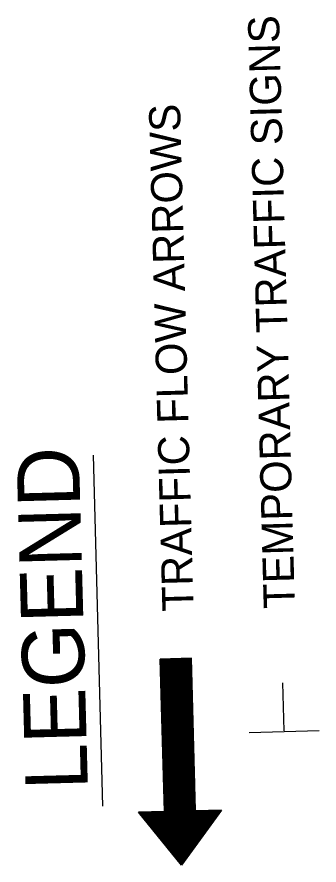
# Model space of a CAD drawing. Extents: x 1929653 to 1931621, y 596452 to 600944.
# Drawn here: x 1930592.3 to 1930650.5, y 599466.7 to 599629.8 of the extents above; entities that cross this region are included whole.
import ezdxf

# ---------------------------------------------------------------- set-up
doc = ezdxf.new("R2010")
doc.units = 0
for name, color, linetype in [('R_Border', 7, 'Continuous'), ('R_Draft', 7, 'Continuous'), ('R_Legend_MOT', 7, 'Continuous')]:
    doc.layers.add(name, color=color, linetype=linetype)

msp = doc.modelspace()

# ---------------------------------------------------------------- linework, layer by layer
at = {"layer": 'R_Border'}
for p, q in [((1930620.05, 599506.36), (1930626.06, 599500.66)), ((1930620.19, 599506.36), (1930626.06, 599500.8)), ((1930620.33, 599506.36), (1930626.05, 599500.94)), ((1930620.47, 599506.37), (1930626.05, 599501.08)), ((1930620.61, 599506.37), (1930626.05, 599501.22)), ((1930620.75, 599506.37), (1930626.04, 599501.36)), ((1930620.9, 599506.38), (1930626.04, 599501.5)), ((1930621.04, 599506.38), (1930626.04, 599501.64)), ((1930621.18, 599506.39), (1930626.03, 599501.79)), ((1930621.32, 599506.39), (1930626.03, 599501.93)), ((1930621.46, 599506.39), (1930626.02, 599502.07)), ((1930621.6, 599506.4), (1930626.02, 599502.21)), ((1930621.74, 599506.4), (1930626.02, 599502.35)), ((1930621.89, 599506.41), (1930626.01, 599502.49)), ((1930622.03, 599506.41), (1930626.01, 599502.63)), ((1930622.17, 599506.41), (1930626.01, 599502.78)), ((1930622.31, 599506.42), (1930626, 599502.92)), ((1930622.45, 599506.42), (1930626, 599503.06)), ((1930622.59, 599506.42), (1930625.99, 599503.2)), ((1930622.73, 599506.43), (1930625.99, 599503.34)), ((1930622.87, 599506.43), (1930625.99, 599503.48)), ((1930623.02, 599506.44), (1930625.98, 599503.62)), ((1930623.16, 599506.44), (1930625.98, 599503.77)), ((1930623.3, 599506.44), (1930625.98, 599503.91)), ((1930623.44, 599506.45), (1930625.97, 599504.05)), ((1930623.58, 599506.45), (1930625.97, 599504.19)), ((1930623.72, 599506.45), (1930625.96, 599504.33)), ((1930623.86, 599506.46), (1930625.96, 599504.47)), ((1930624.01, 599506.46), (1930625.96, 599504.61)), ((1930624.15, 599506.47), (1930625.95, 599504.75)), ((1930624.29, 599506.47), (1930625.95, 599504.9)), ((1930624.43, 599506.47), (1930625.94, 599505.04)), ((1930624.57, 599506.48), (1930625.94, 599505.18)), ((1930624.71, 599506.48), (1930625.94, 599505.32)), ((1930624.85, 599506.48), (1930625.93, 599505.46)), ((1930625, 599506.49), (1930625.93, 599505.6)), ((1930625.14, 599506.49), (1930625.93, 599505.74)), ((1930625.28, 599506.5), (1930625.92, 599505.89)), ((1930625.42, 599506.5), (1930625.92, 599506.03)), ((1930625.56, 599506.5), (1930625.91, 599506.17)), ((1930625.7, 599506.51), (1930625.91, 599506.31)), ((1930625.84, 599506.51), (1930625.91, 599506.45)), ((1930619.92, 599506.34), (1930626.07, 599500.51)), ((1930619.93, 599506.19), (1930626.07, 599500.37)), ((1930619.93, 599506.05), (1930626.07, 599500.23)), ((1930619.93, 599505.91), (1930626.08, 599500.09)), ((1930619.94, 599505.77), (1930626.08, 599499.95)), ((1930619.94, 599505.63), (1930626.09, 599499.81)), ((1930619.95, 599505.49), (1930626.09, 599499.67)), ((1930619.95, 599505.35), (1930626.09, 599499.52)), ((1930619.95, 599505.2), (1930626.1, 599499.38)), ((1930619.96, 599505.06), (1930626.1, 599499.24)), ((1930619.96, 599504.92), (1930626.1, 599499.1)), ((1930619.96, 599504.78), (1930626.11, 599498.96)), ((1930619.97, 599504.64), (1930626.11, 599498.82)), ((1930619.97, 599504.5), (1930626.12, 599498.68)), ((1930619.98, 599504.36), (1930626.12, 599498.53)), ((1930619.98, 599504.22), (1930626.12, 599498.39)), ((1930619.98, 599504.07), (1930626.13, 599498.25)), ((1930619.99, 599503.93), (1930626.13, 599498.11)), ((1930619.99, 599503.79), (1930626.13, 599497.97)), ((1930620, 599503.65), (1930626.14, 599497.83)), ((1930620, 599503.51), (1930626.14, 599497.69)), ((1930620, 599503.37), (1930626.15, 599497.55)), ((1930620.01, 599503.23), (1930626.15, 599497.4)), ((1930620.01, 599503.08), (1930626.15, 599497.26)), ((1930620.01, 599502.94), (1930626.16, 599497.12)), ((1930620.02, 599502.8), (1930626.16, 599496.98)), ((1930620.02, 599502.66), (1930626.16, 599496.84)), ((1930620.03, 599502.52), (1930626.17, 599496.7)), ((1930620.03, 599502.38), (1930626.17, 599496.56)), ((1930620.03, 599502.24), (1930626.18, 599496.41)), ((1930620.04, 599502.09), (1930626.18, 599496.27)), ((1930620.04, 599501.95), (1930626.18, 599496.13)), ((1930620.04, 599501.81), (1930626.19, 599495.99)), ((1930620.05, 599501.67), (1930626.19, 599495.85)), ((1930620.05, 599501.53), (1930626.2, 599495.71)), ((1930620.06, 599501.39), (1930626.2, 599495.57)), ((1930620.06, 599501.25), (1930626.2, 599495.42)), ((1930620.06, 599501.11), (1930626.21, 599495.28)), ((1930620.07, 599500.96), (1930626.21, 599495.14)), ((1930620.07, 599500.82), (1930626.21, 599495)), ((1930620.07, 599500.68), (1930626.22, 599494.86)), ((1930620.08, 599500.54), (1930626.22, 599494.72)), ((1930620.08, 599500.4), (1930626.23, 599494.58)), ((1930620.09, 599500.26), (1930626.23, 599494.43)), ((1930620.09, 599500.12), (1930626.23, 599494.29)), ((1930620.09, 599499.97), (1930626.24, 599494.15)), ((1930620.1, 599499.83), (1930626.24, 599494.01)), ((1930620.1, 599499.69), (1930626.24, 599493.87)), ((1930620.11, 599499.55), (1930626.25, 599493.73)), ((1930620.11, 599499.41), (1930626.25, 599493.59)), ((1930620.11, 599499.27), (1930626.26, 599493.45)), ((1930620.12, 599499.13), (1930626.26, 599493.3)), ((1930620.12, 599498.98), (1930626.26, 599493.16)), ((1930620.12, 599498.84), (1930626.27, 599493.02)), ((1930620.13, 599498.7), (1930626.27, 599492.88)), ((1930620.13, 599498.56), (1930626.27, 599492.74)), ((1930620.14, 599498.42), (1930626.28, 599492.6)), ((1930620.14, 599498.28), (1930626.28, 599492.46)), ((1930620.14, 599498.14), (1930626.29, 599492.31)), ((1930620.15, 599497.99), (1930626.29, 599492.17)), ((1930620.15, 599497.85), (1930626.29, 599492.03)), ((1930620.15, 599497.71), (1930626.3, 599491.89)), ((1930620.16, 599497.57), (1930626.3, 599491.75)), ((1930620.16, 599497.43), (1930626.31, 599491.61)), ((1930620.17, 599497.29), (1930626.31, 599491.47)), ((1930620.17, 599497.15), (1930626.31, 599491.32)), ((1930620.17, 599497.01), (1930626.32, 599491.18)), ((1930620.18, 599496.86), (1930626.32, 599491.04)), ((1930620.18, 599496.72), (1930626.32, 599490.9)), ((1930620.19, 599496.58), (1930626.33, 599490.76)), ((1930620.19, 599496.44), (1930626.33, 599490.62)), ((1930620.19, 599496.3), (1930626.34, 599490.48)), ((1930620.2, 599496.16), (1930626.34, 599490.34)), ((1930620.2, 599496.02), (1930626.34, 599490.19)), ((1930620.2, 599495.87), (1930626.35, 599490.05)), ((1930620.21, 599495.73), (1930626.35, 599489.91)), ((1930620.21, 599495.59), (1930626.35, 599489.77)), ((1930620.22, 599495.45), (1930626.36, 599489.63)), ((1930620.22, 599495.31), (1930626.36, 599489.49)), ((1930620.22, 599495.17), (1930626.37, 599489.35)), ((1930620.23, 599495.03), (1930626.37, 599489.2)), ((1930620.23, 599494.88), (1930626.37, 599489.06)), ((1930620.23, 599494.74), (1930626.38, 599488.92)), ((1930620.24, 599494.6), (1930626.38, 599488.78)), ((1930620.24, 599494.46), (1930626.39, 599488.64)), ((1930620.25, 599494.32), (1930626.39, 599488.5)), ((1930620.25, 599494.18), (1930626.39, 599488.36)), ((1930620.25, 599494.04), (1930626.4, 599488.21)), ((1930620.26, 599493.9), (1930626.4, 599488.07)), ((1930620.26, 599493.75), (1930626.4, 599487.93)), ((1930620.26, 599493.61), (1930626.41, 599487.79)), ((1930620.27, 599493.47), (1930626.41, 599487.65)), ((1930620.27, 599493.33), (1930626.42, 599487.51)), ((1930620.28, 599493.19), (1930626.42, 599487.37)), ((1930620.28, 599493.05), (1930626.42, 599487.23)), ((1930620.28, 599492.91), (1930626.43, 599487.08)), ((1930620.29, 599492.76), (1930626.43, 599486.94)), ((1930620.29, 599492.62), (1930626.43, 599486.8)), ((1930620.3, 599492.48), (1930626.44, 599486.66)), ((1930620.3, 599492.34), (1930626.44, 599486.52)), ((1930620.3, 599492.2), (1930626.45, 599486.38)), ((1930620.31, 599492.06), (1930626.45, 599486.24)), ((1930620.31, 599491.92), (1930626.45, 599486.09)), ((1930620.31, 599491.77), (1930626.46, 599485.95)), ((1930620.32, 599491.63), (1930626.46, 599485.81)), ((1930620.32, 599491.49), (1930626.46, 599485.67)), ((1930620.33, 599491.35), (1930626.47, 599485.53)), ((1930620.33, 599491.21), (1930626.47, 599485.39)), ((1930620.33, 599491.07), (1930626.48, 599485.25)), ((1930620.34, 599490.93), (1930626.48, 599485.1)), ((1930620.34, 599490.78), (1930626.48, 599484.96)), ((1930620.34, 599490.64), (1930626.49, 599484.82)), ((1930620.35, 599490.5), (1930626.49, 599484.68)), ((1930620.35, 599490.36), (1930626.5, 599484.54)), ((1930620.36, 599490.22), (1930626.5, 599484.4)), ((1930620.36, 599490.08), (1930626.5, 599484.26)), ((1930620.36, 599489.94), (1930626.51, 599484.11)), ((1930620.37, 599489.8), (1930626.51, 599483.97)), ((1930620.37, 599489.65), (1930626.51, 599483.83)), ((1930620.37, 599489.51), (1930626.52, 599483.69)), ((1930620.38, 599489.37), (1930626.52, 599483.55)), ((1930620.38, 599489.23), (1930626.53, 599483.41)), ((1930620.39, 599489.09), (1930626.53, 599483.27)), ((1930620.39, 599488.95), (1930626.53, 599483.13)), ((1930620.39, 599488.81), (1930626.54, 599482.98)), ((1930620.4, 599488.66), (1930626.54, 599482.84)), ((1930620.4, 599488.52), (1930626.54, 599482.7)), ((1930620.41, 599488.38), (1930626.55, 599482.56)), ((1930620.41, 599488.24), (1930626.55, 599482.42)), ((1930620.41, 599488.1), (1930626.56, 599482.28)), ((1930620.42, 599487.96), (1930626.56, 599482.14)), ((1930620.42, 599487.82), (1930626.56, 599481.99)), ((1930620.42, 599487.67), (1930626.57, 599481.85)), ((1930620.43, 599487.53), (1930626.57, 599481.71)), ((1930620.43, 599487.39), (1930626.57, 599481.57)), ((1930620.44, 599487.25), (1930626.58, 599481.43)), ((1930620.44, 599487.11), (1930626.58, 599481.29)), ((1930620.44, 599486.97), (1930626.59, 599481.15)), ((1930620.45, 599486.83), (1930626.59, 599481)), ((1930620.45, 599486.69), (1930626.59, 599480.86)), ((1930620.45, 599486.54), (1930626.6, 599480.72)), ((1930620.46, 599486.4), (1930626.6, 599480.58)), ((1930620.46, 599486.26), (1930626.61, 599480.44)), ((1930620.47, 599486.12), (1930626.61, 599480.3)), ((1930620.47, 599485.98), (1930626.61, 599480.16)), ((1930620.47, 599485.84), (1930626.62, 599480.02)), ((1930620.48, 599485.7), (1930626.62, 599479.87)), ((1930620.48, 599485.55), (1930626.62, 599479.73)), ((1930620.48, 599485.41), (1930626.63, 599479.59)), ((1930620.49, 599485.27), (1930626.63, 599479.45)), ((1930620.49, 599485.13), (1930626.64, 599479.31)), ((1930620.5, 599484.99), (1930626.64, 599479.17)), ((1930620.5, 599484.85), (1930626.64, 599479.03)), ((1930620.5, 599484.71), (1930626.65, 599478.88)), ((1930620.51, 599484.56), (1930626.65, 599478.74)), ((1930620.51, 599484.42), (1930626.65, 599478.6)), ((1930620.52, 599484.28), (1930626.66, 599478.46)), ((1930620.52, 599484.14), (1930626.66, 599478.32)), ((1930620.52, 599484), (1930626.67, 599478.18)), ((1930620.53, 599483.86), (1930626.67, 599478.04)), ((1930620.53, 599483.72), (1930626.67, 599477.89)), ((1930620.53, 599483.58), (1930626.68, 599477.75)), ((1930620.54, 599483.43), (1930626.68, 599477.61)), ((1930620.54, 599483.29), (1930626.68, 599477.47)), ((1930620.55, 599483.15), (1930626.69, 599477.33)), ((1930620.55, 599483.01), (1930626.69, 599477.19)), ((1930620.55, 599482.87), (1930629.53, 599474.36)), ((1930620.56, 599482.73), (1930629.47, 599474.28)), ((1930620.56, 599482.59), (1930629.41, 599474.2)), ((1930620.56, 599482.44), (1930629.35, 599474.12)), ((1930620.57, 599482.3), (1930629.29, 599474.04)), ((1930620.57, 599482.16), (1930629.23, 599473.95)), ((1930620.58, 599482.02), (1930629.17, 599473.87)), ((1930620.58, 599481.88), (1930629.11, 599473.79)), ((1930620.58, 599481.74), (1930629.05, 599473.71)), ((1930620.59, 599481.6), (1930629, 599473.63)), ((1930620.59, 599481.45), (1930628.94, 599473.55)), ((1930620.59, 599481.31), (1930628.88, 599473.46)), ((1930620.6, 599481.17), (1930628.82, 599473.38)), ((1930620.6, 599481.03), (1930628.76, 599473.3)), ((1930620.61, 599480.89), (1930628.7, 599473.22)), ((1930620.61, 599480.75), (1930628.64, 599473.14)), ((1930620.61, 599480.61), (1930628.58, 599473.06)), ((1930620.62, 599480.46), (1930628.52, 599472.98)), ((1930620.62, 599480.32), (1930628.46, 599472.89)), ((1930620.63, 599480.18), (1930628.4, 599472.81)), ((1930620.63, 599480.04), (1930628.34, 599472.73)), ((1930620.63, 599479.9), (1930628.28, 599472.65)), ((1930620.64, 599479.76), (1930628.22, 599472.57)), ((1930620.64, 599479.62), (1930628.16, 599472.49)), ((1930620.64, 599479.48), (1930628.1, 599472.41)), ((1930620.65, 599479.33), (1930628.04, 599472.32)), ((1930620.65, 599479.19), (1930627.99, 599472.24)), ((1930620.66, 599479.05), (1930627.93, 599472.16)), ((1930620.66, 599478.91), (1930627.87, 599472.08)), ((1930620.66, 599478.77), (1930627.81, 599472)), ((1930620.34, 599477.01), (1930626.92, 599470.78)), ((1930620.48, 599477.01), (1930626.98, 599470.86)), ((1930620.63, 599477.01), (1930627.04, 599470.94)), ((1930620.67, 599478.63), (1930627.75, 599471.92)), ((1930620.67, 599478.49), (1930627.69, 599471.83)), ((1930620.67, 599478.34), (1930627.63, 599471.75)), ((1930620.68, 599478.2), (1930627.57, 599471.67)), ((1930620.68, 599478.06), (1930627.51, 599471.59)), ((1930620.69, 599477.92), (1930627.45, 599471.51)), ((1930620.69, 599477.78), (1930627.39, 599471.43)), ((1930620.69, 599477.64), (1930627.33, 599471.35)), ((1930620.7, 599477.5), (1930627.27, 599471.26)), ((1930620.7, 599477.35), (1930627.21, 599471.18)), ((1930620.7, 599477.21), (1930627.15, 599471.1)), ((1930620.71, 599477.07), (1930627.09, 599471.02)), ((1930626.7, 599477.18), (1930629.59, 599474.44)), ((1930626.85, 599477.18), (1930629.65, 599474.52)), ((1930626.99, 599477.18), (1930629.71, 599474.61)), ((1930627.13, 599477.19), (1930629.77, 599474.69)), ((1930627.27, 599477.19), (1930629.83, 599474.77)), ((1930627.41, 599477.2), (1930629.89, 599474.85)), ((1930627.55, 599477.2), (1930629.95, 599474.93)), ((1930627.69, 599477.2), (1930630, 599475.01)), ((1930627.84, 599477.21), (1930630.06, 599475.09)), ((1930627.98, 599477.21), (1930630.12, 599475.18)), ((1930628.12, 599477.21), (1930630.18, 599475.26)), ((1930628.26, 599477.22), (1930630.24, 599475.34)), ((1930628.4, 599477.22), (1930630.3, 599475.42)), ((1930628.54, 599477.23), (1930630.36, 599475.5)), ((1930628.68, 599477.23), (1930630.42, 599475.58)), ((1930628.82, 599477.23), (1930630.48, 599475.67)), ((1930628.97, 599477.24), (1930630.54, 599475.75)), ((1930629.11, 599477.24), (1930630.6, 599475.83)), ((1930629.25, 599477.24), (1930630.66, 599475.91)), ((1930629.39, 599477.25), (1930630.72, 599475.99)), ((1930629.53, 599477.25), (1930630.78, 599476.07)), ((1930629.67, 599477.26), (1930630.84, 599476.15)), ((1930629.81, 599477.26), (1930630.9, 599476.24)), ((1930629.96, 599477.26), (1930630.95, 599476.32)), ((1930630.1, 599477.27), (1930631.01, 599476.4)), ((1930630.24, 599477.27), (1930631.07, 599476.48)), ((1930630.38, 599477.28), (1930631.13, 599476.56)), ((1930630.52, 599477.28), (1930631.19, 599476.64)), ((1930630.66, 599477.28), (1930631.25, 599476.72)), ((1930630.8, 599477.29), (1930631.31, 599476.81)), ((1930630.95, 599477.29), (1930631.37, 599476.89)), ((1930631.09, 599477.29), (1930631.43, 599476.97)), ((1930631.23, 599477.3), (1930631.49, 599477.05)), ((1930631.37, 599477.3), (1930631.55, 599477.13)), ((1930631.51, 599477.31), (1930631.61, 599477.21)), ((1930631.65, 599477.31), (1930631.67, 599477.3)), ((1930615.82, 599476.88), (1930625.02, 599468.17)), ((1930615.89, 599476.68), (1930624.96, 599468.09)), ((1930615.96, 599476.89), (1930625.08, 599468.25)), ((1930616.1, 599476.89), (1930625.14, 599468.33)), ((1930616.24, 599476.9), (1930625.19, 599468.41)), ((1930616.38, 599476.9), (1930625.25, 599468.49)), ((1930616.38, 599476.08), (1930624.9, 599468)), ((1930616.53, 599476.9), (1930625.31, 599468.58)), ((1930616.67, 599476.91), (1930625.37, 599468.66)), ((1930616.81, 599476.91), (1930625.43, 599468.74)), ((1930616.87, 599475.47), (1930624.84, 599467.92)), ((1930616.95, 599476.91), (1930625.49, 599468.82)), ((1930617.09, 599476.92), (1930625.55, 599468.9)), ((1930617.23, 599476.92), (1930625.61, 599468.98)), ((1930617.37, 599476.93), (1930625.67, 599469.06)), ((1930617.52, 599476.93), (1930625.73, 599469.15)), ((1930617.66, 599476.93), (1930625.79, 599469.23)), ((1930617.8, 599476.94), (1930625.85, 599469.31)), ((1930617.94, 599476.94), (1930625.91, 599469.39)), ((1930618.08, 599476.95), (1930625.97, 599469.47)), ((1930618.22, 599476.95), (1930626.03, 599469.55)), ((1930618.36, 599476.95), (1930626.09, 599469.63)), ((1930618.5, 599476.96), (1930626.14, 599469.72)), ((1930618.65, 599476.96), (1930626.2, 599469.8)), ((1930618.79, 599476.96), (1930626.26, 599469.88)), ((1930618.93, 599476.97), (1930626.32, 599469.96)), ((1930619.07, 599476.97), (1930626.38, 599470.04)), ((1930619.21, 599476.98), (1930626.44, 599470.12)), ((1930619.35, 599476.98), (1930626.5, 599470.2)), ((1930619.49, 599476.98), (1930626.56, 599470.29)), ((1930619.64, 599476.99), (1930626.62, 599470.37)), ((1930619.78, 599476.99), (1930626.68, 599470.45)), ((1930619.92, 599476.99), (1930626.74, 599470.53)), ((1930620.06, 599477), (1930626.8, 599470.61)), ((1930620.2, 599477), (1930626.86, 599470.69)), ((1930617.36, 599474.87), (1930624.78, 599467.84)), ((1930617.86, 599474.27), (1930624.72, 599467.76)), ((1930618.35, 599473.66), (1930624.66, 599467.68)), ((1930618.84, 599473.06), (1930624.6, 599467.6)), ((1930619.33, 599472.45), (1930624.54, 599467.52)), ((1930619.82, 599471.85), (1930624.48, 599467.43)), ((1930620.31, 599471.25), (1930624.42, 599467.35)), ((1930620.8, 599470.64), (1930624.36, 599467.27)), ((1930621.29, 599470.04), (1930624.3, 599467.19)), ((1930621.79, 599469.44), (1930624.24, 599467.11)), ((1930622.28, 599468.83), (1930624.19, 599467.03)), ((1930622.77, 599468.23), (1930624.13, 599466.95)), ((1930623.26, 599467.63), (1930624.07, 599466.86)), ((1930623.75, 599467.02), (1930624.01, 599466.78))]:
    msp.add_line(p, q, dxfattribs=at)
at = {"layer": 'R_Draft'}
for p, q in [((1930625.91, 599506.51), (1930619.92, 599506.35)), ((1930626.69, 599477.18), (1930625.91, 599506.51)), ((1930620.71, 599477.02), (1930619.92, 599506.35)), ((1930643.76, 599492.57), (1930643.51, 599501.75)), ((1930650.46, 599492.55), (1930637, 599492.19)), ((1930620.71, 599477.02), (1930615.72, 599476.88)), ((1930631.68, 599477.31), (1930623.98, 599466.74)), ((1930631.68, 599477.31), (1930626.69, 599477.18)), ((1930623.98, 599466.74), (1930615.72, 599476.88))]:
    msp.add_line(p, q, dxfattribs=at)
at = {"layer": 'R_Legend_MOT'}
msp.add_line((1930608.88, 599478.04), (1930607.07, 599545.52), dxfattribs=at)

# ---------------------------------------------------------------- texts
for s, height, p in [('TEMPORARY TRAFFIC SIGNS', 6, (1930645.82, 599516.11)), ('TRAFFIC FLOW ARROWS', 6, (1930626.32, 599515.59)), ('LEGEND', 12, (1930605.99, 599481.31))]:
    msp.add_text(s, height=height, rotation=91.5377, dxfattribs=at).set_placement(p)

doc.saveas('drawing.dxf')
